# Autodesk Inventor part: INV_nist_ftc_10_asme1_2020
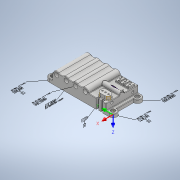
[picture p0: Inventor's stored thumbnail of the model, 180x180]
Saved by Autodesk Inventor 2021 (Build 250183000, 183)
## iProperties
Created: 2016-11
Part Number: INV_nist_ftc_10_asme1_2020
Material: Generic
Document SubType Name: Modeling
Designer: t_liuje
Density: 1 g/cm^3
Appearance: Default
Mass: 187.859 g
Surface Area: 487.851 cm^2
Volume: 187.859 cm^3
Author: t_liuje
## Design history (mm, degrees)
node "Tolerance Features"
  node "Planar Surface 1" dims "d273" = 2.04414 (derived), "d274" = 2.48733 (derived), "d299" = 2.51702 (derived), "d300" = 3.54362 (derived), "d412" = 1.5 (derived), "d413" = 0 (derived), "d414" = 0 (derived), "d978" = 2.99431 (derived), "d979" = 1.44895 (derived), "d980" = 0.2 (derived), "d981" = 0 (derived), "d982" = 0 (derived), "d997" = 3.94736 (derived), "d998" = 10 (derived), "d999" = 0 (derived), "d1001" = 0.25 (derived), "d1002" = 0 (derived), "d1003" = 0 (derived), "d1004" = -22.09829 (derived), "d1005" = 10 (derived), "d1006" = 0 (derived), "d1008" = 0.5 (derived), "d1009" = 0 (derived), "d1010" = 0 (derived)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
  node "Datum Reference Frame 1"
  node "Simple Hole 1" dims "d273" = 2.04414 (derived), "d274" = 2.48733 (derived), "d299" = 2.51702 (derived), "d300" = 3.54362 (derived), "d412" = 1.5 (derived), "d413" = 0 (derived), "d414" = 0 (derived), "d978" = 2.99431 (derived), "d979" = 1.44895 (derived), "d980" = 0.2 (derived), "d981" = 0 (derived), "d982" = 0 (derived), "d997" = 3.94736 (derived), "d998" = 10 (derived), "d999" = 0 (derived), "d1001" = 0.25 (derived), "d1002" = 0 (derived), "d1003" = 0 (derived), "d1004" = -22.09829 (derived), "d1005" = 10 (derived), "d1006" = 0 (derived), "d1008" = 0.5 (derived), "d1009" = 0 (derived), "d1010" = 0 (derived)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
  node "Datum Reference Frame 2"
  node "Simple Hole 2" dims "d273" = 2.04414 (derived), "d274" = 2.48733 (derived), "d299" = 2.51702 (derived), "d300" = 3.54362 (derived), "d412" = 1.5 (derived), "d413" = 0 (derived), "d414" = 0 (derived), "d978" = 2.99431 (derived), "d979" = 1.44895 (derived), "d980" = 0.2 (derived), "d981" = 0 (derived), "d982" = 0 (derived), "d997" = 3.94736 (derived), "d998" = 10 (derived), "d999" = 0 (derived), "d1001" = 0.25 (derived), "d1002" = 0 (derived), "d1003" = 0 (derived), "d1004" = -22.09829 (derived), "d1005" = 10 (derived), "d1006" = 0 (derived), "d1008" = 0.5 (derived), "d1009" = 0 (derived), "d1010" = 0 (derived)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
  node "Datum Reference Frame 3"
  node "Parallel Axes Pattern 1"
  node "Parallel Axes Pattern 2"
  node "General Group 1"
  node "Coplanar Group 1" dims "d273" = 2.04414 (derived), "d274" = 2.48733 (derived), "d299" = 2.51702 (derived), "d300" = 3.54362 (derived), "d412" = 1.5 (derived), "d413" = 0 (derived), "d414" = 0 (derived), "d978" = 2.99431 (derived), "d979" = 1.44895 (derived), "d980" = 0.2 (derived), "d981" = 0 (derived), "d982" = 0 (derived), "d997" = 3.94736 (derived), "d998" = 10 (derived), "d999" = 0 (derived), "d1001" = 0.25 (derived), "d1002" = 0 (derived), "d1003" = 0 (derived), "d1004" = -22.09829 (derived), "d1005" = 10 (derived), "d1006" = 0 (derived), "d1008" = 0.5 (derived), "d1009" = 0 (derived), "d1010" = 0 (derived)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
  node "Datum Reference Frame 4"
  node "Datum Reference Frame 5"
  node "Simple Hole 13" dims "d273" = 2.04414 (derived), "d274" = 2.48733 (derived), "d299" = 2.51702 (derived), "d300" = 3.54362 (derived), "d412" = 1.5 (derived), "d413" = 0 (derived), "d414" = 0 (derived), "d978" = 2.99431 (derived), "d979" = 1.44895 (derived), "d980" = 0.2 (derived), "d981" = 0 (derived), "d982" = 0 (derived), "d997" = 3.94736 (derived), "d998" = 10 (derived), "d999" = 0 (derived), "d1001" = 0.25 (derived), "d1002" = 0 (derived), "d1003" = 0 (derived), "d1004" = -22.09829 (derived), "d1005" = 10 (derived), "d1006" = 0 (derived), "d1008" = 0.5 (derived), "d1009" = 0 (derived), "d1010" = 0 (derived)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
  node "Datum Reference Frame 6"
  node "Datum Reference Frame 12"
  node "Simple Hole 14" dims "d273" = 2.04414 (derived), "d274" = 2.48733 (derived), "d299" = 2.51702 (derived), "d300" = 3.54362 (derived), "d412" = 1.5 (derived), "d413" = 0 (derived), "d414" = 0 (derived), "d978" = 2.99431 (derived), "d979" = 1.44895 (derived), "d980" = 0.2 (derived), "d981" = 0 (derived), "d982" = 0 (derived), "d997" = 3.94736 (derived), "d998" = 10 (derived), "d999" = 0 (derived), "d1001" = 0.25 (derived), "d1002" = 0 (derived), "d1003" = 0 (derived), "d1004" = -22.09829 (derived), "d1005" = 10 (derived), "d1006" = 0 (derived), "d1008" = 0.5 (derived), "d1009" = 0 (derived), "d1010" = 0 (derived)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
  node "Datum Reference Frame 7"
  node "Datum Reference Frame 18"
  node "Datum Reference Frame 13"
  node "Simple Hole 15" dims "d273" = 2.04414 (derived), "d274" = 2.48733 (derived), "d299" = 2.51702 (derived), "d300" = 3.54362 (derived), "d412" = 1.5 (derived), "d413" = 0 (derived), "d414" = 0 (derived), "d978" = 2.99431 (derived), "d979" = 1.44895 (derived), "d980" = 0.2 (derived), "d981" = 0 (derived), "d982" = 0 (derived), "d997" = 3.94736 (derived), "d998" = 10 (derived), "d999" = 0 (derived), "d1001" = 0.25 (derived), "d1002" = 0 (derived), "d1003" = 0 (derived), "d1004" = -22.09829 (derived), "d1005" = 10 (derived), "d1006" = 0 (derived), "d1008" = 0.5 (derived), "d1009" = 0 (derived), "d1010" = 0 (derived)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
  node "Datum Reference Frame 8"
  node "Datum Reference Frame 19"
  node "Datum Reference Frame 14"
  node "Planar Surface 10" dims "d273" = 2.04414 (derived), "d274" = 2.48733 (derived), "d299" = 2.51702 (derived), "d300" = 3.54362 (derived), "d412" = 1.5 (derived), "d413" = 0 (derived), "d414" = 0 (derived), "d978" = 2.99431 (derived), "d979" = 1.44895 (derived), "d980" = 0.2 (derived), "d981" = 0 (derived), "d982" = 0 (derived), "d997" = 3.94736 (derived), "d998" = 10 (derived), "d999" = 0 (derived), "d1001" = 0.25 (derived), "d1002" = 0 (derived), "d1003" = 0 (derived), "d1004" = -22.09829 (derived), "d1005" = 10 (derived), "d1006" = 0 (derived), "d1008" = 0.5 (derived), "d1009" = 0 (derived), "d1010" = 0 (derived)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
  node "Datum Reference Frame 9"
  node "Planar Surface 11" dims "d273" = 2.04414 (derived), "d274" = 2.48733 (derived), "d299" = 2.51702 (derived), "d300" = 3.54362 (derived), "d412" = 1.5 (derived), "d413" = 0 (derived), "d414" = 0 (derived), "d978" = 2.99431 (derived), "d979" = 1.44895 (derived), "d980" = 0.2 (derived), "d981" = 0 (derived), "d982" = 0 (derived), "d997" = 3.94736 (derived), "d998" = 10 (derived), "d999" = 0 (derived), "d1001" = 0.25 (derived), "d1002" = 0 (derived), "d1003" = 0 (derived), "d1004" = -22.09829 (derived), "d1005" = 10 (derived), "d1006" = 0 (derived), "d1008" = 0.5 (derived), "d1009" = 0 (derived), "d1010" = 0 (derived)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
  node "Datum Reference Frame 10"
  node "Planar Surface 12" dims "d273" = 2.04414 (derived), "d274" = 2.48733 (derived), "d299" = 2.51702 (derived), "d300" = 3.54362 (derived), "d412" = 1.5 (derived), "d413" = 0 (derived), "d414" = 0 (derived), "d978" = 2.99431 (derived), "d979" = 1.44895 (derived), "d980" = 0.2 (derived), "d981" = 0 (derived), "d982" = 0 (derived), "d997" = 3.94736 (derived), "d998" = 10 (derived), "d999" = 0 (derived), "d1001" = 0.25 (derived), "d1002" = 0 (derived), "d1003" = 0 (derived), "d1004" = -22.09829 (derived), "d1005" = 10 (derived), "d1006" = 0 (derived), "d1008" = 0.5 (derived), "d1009" = 0 (derived), "d1010" = 0 (derived)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
  node "Datum Reference Frame 11"
  node "Datum Reference Frame 15"
  node "Parallel Axes Pattern 3"
  node "Coplanar Group 2"
  node "Parallel Axes Pattern 4"
  node "Simple Hole 23"
  node "Parallel Axes Pattern 5"
  node "Slot 1" dims "d273" = 2.04414 (derived), "d274" = 2.48733 (derived), "d299" = 2.51702 (derived), "d300" = 3.54362 (derived), "d412" = 1.5 (derived), "d413" = 0 (derived), "d414" = 0 (derived), "d978" = 2.99431 (derived), "d979" = 1.44895 (derived), "d980" = 0.2 (derived), "d981" = 0 (derived), "d982" = 0 (derived), "d997" = 3.94736 (derived), "d998" = 10 (derived), "d999" = 0 (derived), "d1001" = 0.25 (derived), "d1002" = 0 (derived), "d1003" = 0 (derived), "d1004" = -22.09829 (derived), "d1005" = 10 (derived), "d1006" = 0 (derived), "d1008" = 0.5 (derived), "d1009" = 0 (derived), "d1010" = 0 (derived)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
  node "Datum Reference Frame 16"
  node "Datum Reference Frame 17"
  node "Slab 1"
  node "Parallel Axes Pattern 6"
  node "Cylindrical Surface 10"
  node "Parallel Axes Pattern 7"
  node "Parallel Axes Pattern 8"
  node "Parallel Axes Pattern 9"
  node "Parallel Axes Pattern 10"
  node "Simple Hole 51"
  node "Extruded Group 1"
sketch "Sketch1"
  geometry: L1 (-62.5, 23)-(-62.5, 0); L2 (-62.5, 23)-(-22, 23); L3 (-62.5, 0)-(62.5, 0); L4 (62.5, 23)-(60, 23); L5 (62.5, 0)-(62.5, 23); L6 (80.303, 0)-(-60.812, 0); L7 (0, 48.078)-(0, -29.626); C1 r 3.5 at (-14, 23); C2 r 3.5 at (8, 23); C3 r 3.5 at (30, 23); C4 r 3.5 at (52, 23); A1 r 8 centre (-14, 23) between (-9.707, 29.751) and (-22, 23); A2 r 12.5 centre (-3, 40.299) between (-9.707, 29.751) and (3.707, 29.751); A3 r 8 centre (8, 23) between (12.293, 29.751) and (3.707, 29.751); A4 r 12.5 centre (19, 40.299) between (12.293, 29.751) and (25.707, 29.751); A5 r 8 centre (30, 23) between (34.293, 29.751) and (25.707, 29.751); A6 r 12.5 centre (41, 40.299) between (34.293, 29.751) and (47.707, 29.751); A7 r 8 centre (52, 23) between (60, 23) and (47.707, 29.751); 1 further point
  constraints: 14 end point, 14 point on circle, 11 centre point, 8 equal radius, 7 point on line, 6 tangent, 4 coincident, 2 collinear, 2 horizontal, 2 vertical, 1 other
  dimensions: "d0" = 125 distance of L1.end L3.end; "d1" = 10.5 distance from line of L5 A7.centre; "d2" = 23 distance of L1.start L1.end; "d3" = 8 radius of A7; "d4" = 22 distance of C3.centre C4.centre (= d5); "d5" = 22 distance of A1.centre A3.centre; "d6" = 22 distance of C3.centre A3.centre (= d5); "d7" = 12.5 radius of A6; "d8" = 7 diameter of C4
extrude "Extrusion1" new body sketch "Sketch1" stored distance "d9" = 75; taper "d10" = 0 deg
sketch "Sketch2"
  geometry: L1 (125, 0)-(125, -75) reference; L2 (0, 0)-(125, 0) reference; L3 (0, -75)-(0, 0) reference; L4 (125, -75)-(0, -75) reference; L5 (125, 0)-(132.5, 0); L6 (132.5, -18)-(132.5, -57); L7 (132.5, -75)-(125, -75); L8 (125, -75)-(125, 0); L9 (0, 0)-(-7.5, 0); L10 (-7.5, -18)-(-7.5, -57); L11 (-7.5, -75)-(0, -75); L12 (0, -75)-(0, 0); A1 r 9 centre (132.5, -9) between (132.5, -18) and (132.5, 0); A2 r 9 centre (132.5, -66) between (132.5, -75) and (132.5, -57); A3 r 9 centre (-7.5, -9) between (-7.5, 0) and (-7.5, -18); A4 r 9 centre (-7.5, -66) between (-7.5, -57) and (-7.5, -75); 1 further point
  constraints: 16 end point, 8 point on circle, 4 centre point, 4 parallel, 4 point on line, 4 tangent, 3 equal radius, 2 collinear, 2 horizontal, 2 perpendicular
  dimensions: "d11" = 7.5 distance of L1.start L5.end; "d12" = 18 distance of L6.start L5.end; "d13" = 18 distance of L6.end L7.start
extrude "Extrusion2" join sketch "Sketch2" distance "d14" = 8; taper "d15" = 0 deg
sketch "Sketch3"
  geometry: L1 (21, -53.5)-(30, -53.5); L2 (30, -68.5)-(21, -68.5); L3 (40.5, -75)-(0, -75) reference; L4 (40.5, 0)-(40.5, -75) reference; A1 r 7.5 centre (30, -61) between (30, -68.5) and (30, -53.5); A2 r 7.5 centre (21, -61) between (21, -53.5) and (21, -68.5); 1 further point
  constraints: 4 end point, 4 point on circle, 4 tangent, 2 centre point, 1 horizontal, 1 parallel
  dimensions: "d16" = 9 distance of L2.start L2.end; "d17" = 15 distance of L1.end L2.start; "d18" = 6.5 distance between parallel lines of L3 L2; "d19" = 10.5 distance from line of L4 A1.centre
extrude "Extrusion3" join sketch "Sketch3" distance "d20" = 8; taper "d21" = 0 deg
sketch "Sketch4"
  geometry: L1 (33, -75)-(33, -70); L2 (33, -70)-(28, -70); L3 (28, -70)-(28, -74); L4 (28, -74)-(23, -74); L5 (23, -74)-(23, -70); L6 (23, -70)-(18, -70); L7 (18, -70)-(18, -75); L8 (18, -75)-(33, -75); L9 (40.5, -75)-(0, -75) reference; L10 (40.5, 0)-(40.5, -75) reference; 1 further point
  constraints: 16 end point, 5 perpendicular, 2 collinear, 2 point on line, 1 vertical
  dimensions: "d22" = 5 distance of L1.start L1.end; "d23" = 5 distance of L1.end L2.end; "d24" = 4 distance of L2.end L3.end; "d25" = 5 distance of L3.end L4.end; "d26" = 5 distance of L5.end L6.end; "d27" = 7.5 distance between parallel lines of L10 L1
extrude "Extrusion4" cut sketch "Sketch4" stored distance "d28" = 8; taper "d29" = 0 deg
sketch "Sketch5"
  geometry: L1 (7.5, -5)-(37.5, -5); L2 (37.5, -5)-(37.5, -20); L3 (37.5, -20)-(7.5, -20); L4 (7.5, -20)-(7.5, -5); L5 (0, 0)-(40.5, 0) reference; L6 (40.5, 0)-(40.5, -75) reference; 1 further point
  constraints: 8 end point, 2 parallel, 1 horizontal, 1 perpendicular
  dimensions: "d30" = 30 distance of L2.end L3.end; "d31" = 15 distance of L1.end L2.end; "d32" = 5 distance between parallel lines of L1 L5; "d33" = 3 distance between parallel lines of L2 L6
extrude "Extrusion5" join sketch "Sketch5" distance "d34" = 4; taper "d35" = 0 deg
sketch "Sketch6"
  geometry: L1 (7.5, -5)-(37.5, -5) reference; L2 (7.5, -20)-(7.5, -5) reference; L3 (37.5, -5)-(37.5, -20) reference; L4 (37.5, -20)-(7.5, -20) reference; L5 (15.5, -5)-(18.5, -5); L6 (18.5, -5)-(18.5, -20); L7 (18.5, -20)-(15.5, -20); L8 (15.5, -20)-(15.5, -5); L9 (26.5, -5)-(29.5, -5); L10 (29.5, -5)-(29.5, -20); L11 (29.5, -20)-(26.5, -20); L12 (26.5, -20)-(26.5, -5); 1 further point
  constraints: 16 end point, 4 parallel, 4 point on line, 2 horizontal, 2 perpendicular
  dimensions: "d36" = 3 distance between parallel lines of L10 L12; "d37" = 8 distance between parallel lines of L3 L10; "d38" = 8 distance between parallel lines of L12 L6; "d39" = 3 distance between parallel lines of L8 L6
extrude "Extrusion6" cut sketch "Sketch6" distance "d40" = 1.5; taper "d41" = 0 deg
sketch "Sketch7"
  geometry: L1 (0, 75)-(0, 0) reference; A1 r 6 centre (0, 37.5) between (0, 43.5) and (0, 31.5); 1 further point
  constraints: 2 point on circle, 2 point on line, 1 centre point, 1 midpoint
  dimensions: "d42" = 12 diameter of A1
extrude "Extrusion7" join sketch "Sketch7" stored distance "d43" = 1.5; taper "d44" = 0 deg; dims "d4" = 22 (= d5)
fillet "Fillet1" dims "d45" = 1
sketch "Sketch11"
  geometry: A1 r 9 centre (-132.5, -9) between (-132.5, 0) and (-132.5, -18) reference; 3 further points
  constraints: 2 coincident
hole "Hole2" sketch "Sketch11" diameter "d57" = 6; stored, may be unused: countersink angle "d61" = 90 deg, drill point angle "d63" = 0 deg; dims "d58" = 6, "d59" = 10, "d60" = 2, "d62" = 8
sketch "Sketch12"
  geometry: C1 r 3.5 at (-52, -23) reference; C2 r 3.5 at (-30, -23) reference; C3 r 3.5 at (-8, -23) reference; C4 r 3.5 at (14, -23) reference; 4 further points
  constraints: 4 coincident
hole "Hole6" sketch "Sketch12" at (-52, -23), (-30, -23), (-8, -23), (14, -23) diameter "d93" = 10; stored, may be unused: countersink angle "d97" = 90 deg, drill point angle "d99" = 0 deg; dims "d94" = 6, "d95" = 10, "d96" = 2, "d98" = 10
hole "Hole7" diameter "d102" = 3.5; stored, may be unused: countersink angle "d106" = 90 deg, drill point angle "d108" = 0 deg; dims "d100" = 14, "d101" = 8, "d103" = 6, "d104" = 10, "d105" = 2, "d107" = 10.25
pattern_linear "Rectangular Pattern1" dims "d111" = 7
sketch "Sketch18" dims "d944" = 10
  geometry: L1 (29.5, -20)-(36.5, -20) reference; L2 (37.5, -19)-(37.5, -6) reference; C1 r 1.75 at (11.5, -12.5); C2 r 1.75 at (33.5, -12.5); 3 further points
  constraints: 2 centre point, 2 coincident, 1 horizontal, 2 other
  dimensions: "d112" = 7.5 distance from line of L1 point (33.5, -12.5); "d113" = 4 distance from line of L2 point (33.5, -12.5); "d941" = 11 distance of point (33.5, -12.5) point (22.5, -12.5); "d1056" = 3.5 diameter of C1; "d1069" = 3.5 diameter of C2
sketch "Sketch15"
  geometry: L1 (37.5, -19)-(37.5, -6) reference; L2 (29.5, -20)-(36.5, -20) reference; L3 (29.5, -5)-(29.5, -20) reference; L4 (29.5, -5)-(29.5, -20) reference; L5 (29.5, -16.191)-(37.5, -16.191); L6 (33.5, -16.191)-(33.5, -8.753); L7 (29.5, -12.5)-(36.185, -12.5); L8 (29.5, -20)-(29.5, -5); 2 further points
  constraints: 8 end point, 2 midpoint, 2 point on line, 2 symmetric about line, 1 horizontal, 1 perpendicular, 1 vertical
  dimensions: "d121" = 2.4 distance from line of L1 point (35.1, -17.5); "d122" = 2.5 distance from line of L2 point (35.1, -17.5)
hole "Hole9" sketch "Sketch15" at (35.1, -17.5), (31.9, -7.5) diameter "d123" = 2.459; stored, may be unused: countersink angle "d127" = 90 deg, drill point angle "d129" = 118 deg; dims "d124" = 6, "d125" = 10, "d126" = 2, "d128" = 12
sketch "Sketch8"
  geometry: L1 (-12, -5.5)-(-90, -5.5); L2 (-90, -5.5)-(-90, 44.5); L3 (-90, 44.5)-(-12, 44.5); L4 (-12, 44.5)-(-12, -5.5); L5 (0, 0)-(0, 39) reference; L6 (-110, -18)-(0, -18) reference; 1 further point
  constraints: 8 end point, 2 parallel, 1 horizontal, 1 perpendicular
  dimensions: "d142" = 78 distance of L2.end L3.end; "d143" = 50 distance of L1.end L2.end; "d144" = 12 distance between parallel lines of L5 L4; "d145" = 12.5 distance between parallel lines of L1 L6
extrude "Extrusion8" cut sketch "Sketch8" distance "d146" = 17; taper "d147" = 0 deg
fillet "Fillet2" dims "d148" = 2
hole "Hole11" diameter "d151" = 2.5; stored, may be unused: countersink angle "d155" = 90 deg, drill point angle "d157" = 118 deg; dims "d149" = 22, "d150" = 18, "d152" = 6, "d153" = 10, "d154" = 2, "d156" = 12
pattern_linear "Rectangular Pattern3" dims "d160" = 22, "d163" = 31
hole "Hole12" diameter "d287" = 5.5; stored, may be unused: countersink angle "d291" = 90 deg, drill point angle "d293" = 118 deg; dims "d285" = 14, "d286" = 5, "d288" = 6, "d289" = 4, "d290" = 2, "d292" = 27.5
hole "Hole13" diameter "d330" = 5.5; stored, may be unused: countersink angle "d334" = 90 deg, drill point angle "d336" = 118 deg; dims "d328" = 8.062, "d329" = 12.54, "d331" = 6, "d332" = 4, "d333" = 2, "d335" = 35
workplane "Work Plane2"
sketch "Sketch9"
  geometry: L1 (-26.77, 0)-(-11.77, 0)
  constraints: 2 end point, 1 horizontal
  dimensions: "d370" = 15 distance of L1.start L1.end
workplane "Work Plane3"
workplane "Work Plane4"
workplane "Work Plane5"
workplane "Work Plane6"
workplane "Work Plane7"
workplane "Work Plane8"
sketch "Sketch10"
  geometry: 1 further point
fillet "Fillet3" dims "d870" = 0.15
sketch "Sketch13"
  geometry: C1 r 3.5 at (14, 23) reference; C2 r 3.5 at (-8, 23) reference; C3 r 3.5 at (-30, 23) reference; C4 r 3.5 at (-52, 23) reference; 5 further points
  constraints: 4 coincident
hole "Hole14" sketch "Sketch13" at (14, 23), (-8, 23), (-30, 23), (-52, 23) diameter "d901" = 10; stored, may be unused: countersink angle "d905" = 90 deg, drill point angle "d907" = 0 deg; dims "d902" = 6, "d903" = 4, "d904" = 2, "d906" = 10
mirror "Mirror3"
sketch "Sketch14"
  geometry: C1 r 3 at (7.5, -9) reference; C2 r 3 at (-132.5, -9) reference; C3 r 3 at (-132.5, -9) reference; C4 r 3 at (7.5, -9) reference; C5 r 3 at (-132.5, -66) reference; C6 r 3 at (7.5, -66) reference; 5 further points
  constraints: 4 coincident
hole "Hole15" sketch "Sketch14" at (7.5, -9), (7.5, -66), (-132.5, -66), (-132.5, -9) diameter "d908" = 10; stored, may be unused: countersink angle "d912" = 90 deg, drill point angle "d914" = 0 deg; dims "d909" = 6, "d910" = 4, "d911" = 2, "d913" = 2
fillet "Fillet4" dims "d875" = 0.2
sketch "Sketch16"
  geometry: L1 (26.5, -19)-(26.5, -6); L2 (7.5, -20)-(25.5, -20); L3 (29.5, -20)-(26.5, -20) reference; L4 (18.5, -20)-(26.5, -20) reference; L5 (26.5, -5)-(18.5, -5) reference; L6 (18.5, -5)-(18.5, -20) reference; 3 further points
  constraints: 4 end point
  dimensions: "d915" = 2.4 distance from line of L1 point (24.1, -17.5); "d916" = 2.5 distance from line of L2 point (24.1, -17.5); "d917" = 2.5 distance from line of L5 point (20.9, -7.5); "d918" = 2.4 distance from line of L6 point (20.9, -7.5)
hole "Hole16" sketch "Sketch16" at (24.1, -17.5), (20.9, -7.5) diameter "d919" = 2.459; stored, may be unused: countersink angle "d923" = 90 deg, drill point angle "d925" = 118 deg; dims "d920" = 6, "d921" = 4, "d922" = 2, "d924" = 12
sketch "Sketch17"
  geometry: L1 (37.5, -19)-(37.5, -6); L2 (29.5, -20)-(36.5, -20); L3 (29.5, -5)-(29.5, -20); L4 (29.5, -5)-(29.5, -20); L5 (29.5, -16.191)-(37.5, -16.191); L6 (33.5, -16.191)-(33.5, -8.753); L7 (29.5, -12.5)-(36.185, -12.5); L8 (29.5, -20)-(29.5, -5); L9 (15.5, -19)-(15.5, -6); L10 (7.5, -20)-(14.5, -20); L11 (29.5, -20)-(26.5, -20); L12 (7.5, -20)-(15.5, -20); L13 (15.5, -5)-(7.5, -5); L14 (7.5, -5)-(7.5, -20); L15 (15.5, -20)-(15.5, -5) reference; C1 r 1.75 at (22.5, -12.5); 7 further points
  constraints: 28 end point, 2 midpoint, 2 point on line, 2 symmetric about line, 1 centre point, 1 coincident, 1 horizontal, 1 perpendicular, 1 vertical
  dimensions: "d926" = 2.4 distance from line of L1 point (35.1, -17.5); "d927" = 2.5 distance from line of L2 point (35.1, -17.5); "d928" = 2.4 distance from line of L9 point (13.1, -17.5); "d929" = 2.5 distance from line of L10 point (13.1, -17.5); "d930" = 2.5 distance from line of L13 point (9.9, -7.5); "d931" = 2.4 distance from line of L14 point (9.9, -7.5); "d1066" = 3.5 diameter of C1 (derived)
hole "Hole17" sketch "Sketch17" diameter "d932" = 2.459; stored, may be unused: countersink angle "d936" = 90 deg, drill point angle "d938" = 118 deg; dims "d933" = 6, "d934" = 4, "d935" = 2, "d937" = 12
extrude "Extrusion10" cut sketch "Sketch18" distance "d1057" = 9.25; taper "d1058" = 0 deg
extrude "Extrusion11" cut sketch "Sketch17" distance "d1067" = 9.25; taper "d1068" = 0 deg
extrude "Extrusion12" cut sketch "Sketch18" distance "d1070" = 9.25; taper "d1071" = 0 deg
sketch "Sketch20"
  geometry: L1 (-1.061, 8)-(5.303, 8) reference; L2 (3.544, 8)-(-4.428, 8); L3 (-4.428, 8)-(-4.428, -0.058); L4 (-4.428, -0.058)-(3.544, -0.058); L5 (3.544, -0.058)-(3.544, 8); 1 further point
  constraints: 8 end point, 2 parallel, 1 horizontal, 1 perpendicular, 1 point on line
patch "Boundary Patch1" sketch "Sketch20"
sketch "Sketch21"
  geometry: L1 (7.5, 8)-(-5.303, 8) reference; L2 (-8.827, 0)-(18.436, 0) reference; L3 (-1.99, 8)-(4.804, 8); L4 (4.804, 8)-(4.804, 0); L5 (4.804, 0)-(-1.99, 0); L6 (-1.99, 0)-(-1.99, 8); 2 further points
  constraints: 8 end point, 2 parallel, 1 horizontal, 1 midpoint, 1 perpendicular, 1 point on line
patch "Boundary Patch2" sketch "Sketch21"
body "Solid1"
node "Annotations"
node "Projected Loop1"
body "Srf1"
body "Srf2"
node "Leader Text 3"
node "Leader Text 6"
node "General Note 1"
node "General Surface Profile Tolerance"
node "Feature Control Frame 30"
node "Datum Identifier 1" dims "d5" = 22, "d273" = 2.04414 (derived), "d274" = 2.48733 (derived), "d299" = 2.51702 (derived), "d300" = 3.54362 (derived), "d412" = 1.5 (derived), "d413" = 0 (derived), "d414" = 0 (derived), "d978" = 2.99431 (derived), "d979" = 1.44895 (derived), "d980" = 0.2 (derived), "d981" = 0 (derived), "d982" = 0 (derived), "d997" = 3.94736 (derived), "d998" = 10 (derived), "d999" = 0 (derived), "d1001" = 0.25 (derived), "d1002" = 0 (derived), "d1003" = 0 (derived), "d1004" = -22.09829 (derived), "d1005" = 10 (derived), "d1006" = 0 (derived), "d1008" = 0.5 (derived), "d1009" = 0 (derived)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
node "Hole Note 1" dims "d5" = 22
node "Feature Control Frame 31"
node "Datum Identifier 2" dims "d5" = 22, "d273" = 2.04414 (derived), "d274" = 2.48733 (derived), "d299" = 2.51702 (derived), "d300" = 3.54362 (derived), "d412" = 1.5 (derived), "d413" = 0 (derived), "d414" = 0 (derived), "d978" = 2.99431 (derived), "d979" = 1.44895 (derived), "d980" = 0.2 (derived), "d981" = 0 (derived), "d982" = 0 (derived), "d997" = 3.94736 (derived), "d998" = 10 (derived), "d999" = 0 (derived), "d1001" = 0.25 (derived), "d1002" = 0 (derived), "d1003" = 0 (derived), "d1004" = -22.09829 (derived), "d1005" = 10 (derived), "d1006" = 0 (derived), "d1008" = 0.5 (derived), "d1009" = 0 (derived)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
node "Hole Note 2" dims "d5" = 22
node "Feature Control Frame 32"
node "Datum Identifier 3" dims "d5" = 22, "d273" = 2.04414 (derived), "d274" = 2.48733 (derived), "d299" = 2.51702 (derived), "d300" = 3.54362 (derived), "d412" = 1.5 (derived), "d413" = 0 (derived), "d414" = 0 (derived), "d978" = 2.99431 (derived), "d979" = 1.44895 (derived), "d980" = 0.2 (derived), "d981" = 0 (derived), "d982" = 0 (derived), "d997" = 3.94736 (derived), "d998" = 10 (derived), "d999" = 0 (derived), "d1001" = 0.25 (derived), "d1002" = 0 (derived), "d1003" = 0 (derived), "d1004" = -22.09829 (derived), "d1005" = 10 (derived), "d1006" = 0 (derived), "d1008" = 0.5 (derived), "d1009" = 0 (derived)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
node "Simple Hole 3"
node "Simple Hole 4"
node "Hole Note 3" dims "d5" = 22
node "Feature Control Frame 33"
node "Simple Hole 5"
node "Simple Hole 6"
node "Simple Hole 7"
node "Simple Hole 8"
node "Simple Hole 9"
node "Simple Hole 10"
node "Simple Hole 11"
node "Simple Hole 12"
node "Hole Note 4" dims "d5" = 22
node "Feature Control Frame 34"
node "Planar Surface 2"
node "Planar Surface 3"
node "Cylindrical Surface 1"
node "Cylindrical Surface 2"
node "Cylindrical Surface 3"
node "Spherical Surface 1"
node "Planar Surface 4"
node "Cylindrical Surface 4"
node "Planar Surface 5"
node "Cylindrical Surface 5"
node "Spherical Surface 2"
node "Cylindrical Surface 6"
node "Cylindrical Surface 7"
node "Planar Surface 6"
node "Spherical Surface 3"
node "Spherical Surface 4"
node "Cylindrical Surface 8"
node "Feature Control Frame 35"
node "Leader Text 7"
node "Planar Surface 7"
node "Planar Surface 8"
node "Planar Surface 9"
node "Feature Control Frame 36"
node "Datum Identifier 4" dims "d5" = 22, "d273" = 2.04414 (derived), "d274" = 2.48733 (derived), "d299" = 2.51702 (derived), "d300" = 3.54362 (derived), "d412" = 1.5 (derived), "d413" = 0 (derived), "d414" = 0 (derived), "d978" = 2.99431 (derived), "d979" = 1.44895 (derived), "d980" = 0.2 (derived), "d981" = 0 (derived), "d982" = 0 (derived), "d997" = 3.94736 (derived), "d998" = 10 (derived), "d999" = 0 (derived), "d1001" = 0.25 (derived), "d1002" = 0 (derived), "d1003" = 0 (derived), "d1004" = -22.09829 (derived), "d1005" = 10 (derived), "d1006" = 0 (derived), "d1008" = 0.5 (derived), "d1009" = 0 (derived)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
node "Leader Text 8"
node "Diameter Dimension 1" dims "d5" = 22, "d1089" = 3.5 (derived)
node "Feature Control Frame 40"
node "Datum Identifier 5" dims "d5" = 22, "d273" = 2.04414 (derived), "d274" = 2.48733 (derived), "d299" = 2.51702 (derived), "d300" = 3.54362 (derived), "d412" = 1.5 (derived), "d413" = 0 (derived), "d414" = 0 (derived), "d978" = 2.99431 (derived), "d979" = 1.44895 (derived), "d980" = 0.2 (derived), "d981" = 0 (derived), "d982" = 0 (derived), "d997" = 3.94736 (derived), "d998" = 10 (derived), "d999" = 0 (derived), "d1001" = 0.25 (derived), "d1002" = 0 (derived), "d1003" = 0 (derived), "d1004" = -22.09829 (derived), "d1005" = 10 (derived), "d1006" = 0 (derived), "d1008" = 0.5 (derived), "d1009" = 0 (derived)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
node "Diameter Dimension 2" dims "d5" = 22, "d1099" = 3.5 (derived)
node "Feature Control Frame 41"
node "Datum Identifier 6" dims "d5" = 22, "d273" = 2.04414 (derived), "d274" = 2.48733 (derived), "d299" = 2.51702 (derived), "d300" = 3.54362 (derived), "d412" = 1.5 (derived), "d413" = 0 (derived), "d414" = 0 (derived), "d978" = 2.99431 (derived), "d979" = 1.44895 (derived), "d980" = 0.2 (derived), "d981" = 0 (derived), "d982" = 0 (derived), "d997" = 3.94736 (derived), "d998" = 10 (derived), "d999" = 0 (derived), "d1001" = 0.25 (derived), "d1002" = 0 (derived), "d1003" = 0 (derived), "d1004" = -22.09829 (derived), "d1005" = 10 (derived), "d1006" = 0 (derived), "d1008" = 0.5 (derived), "d1009" = 0 (derived)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
node "Diameter Dimension 3" dims "d5" = 22, "d1109" = 3.5 (derived)
node "Feature Control Frame 42"
node "Datum Identifier 7" dims "d5" = 22, "d273" = 2.04414 (derived), "d274" = 2.48733 (derived), "d299" = 2.51702 (derived), "d300" = 3.54362 (derived), "d412" = 1.5 (derived), "d413" = 0 (derived), "d414" = 0 (derived), "d978" = 2.99431 (derived), "d979" = 1.44895 (derived), "d980" = 0.2 (derived), "d981" = 0 (derived), "d982" = 0 (derived), "d997" = 3.94736 (derived), "d998" = 10 (derived), "d999" = 0 (derived), "d1001" = 0.25 (derived), "d1002" = 0 (derived), "d1003" = 0 (derived), "d1004" = -22.09829 (derived), "d1005" = 10 (derived), "d1006" = 0 (derived), "d1008" = 0.5 (derived), "d1009" = 0 (derived)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
node "Feature Control Frame 43"
node "Datum Identifier 8" dims "d5" = 22, "d273" = 2.04414 (derived), "d274" = 2.48733 (derived), "d299" = 2.51702 (derived), "d300" = 3.54362 (derived), "d412" = 1.5 (derived), "d413" = 0 (derived), "d414" = 0 (derived), "d978" = 2.99431 (derived), "d979" = 1.44895 (derived), "d980" = 0.2 (derived), "d981" = 0 (derived), "d982" = 0 (derived), "d997" = 3.94736 (derived), "d998" = 10 (derived), "d999" = 0 (derived), "d1001" = 0.25 (derived), "d1002" = 0 (derived), "d1003" = 0 (derived), "d1004" = -22.09829 (derived), "d1005" = 10 (derived), "d1006" = 0 (derived), "d1008" = 0.5 (derived), "d1009" = 0 (derived)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
node "Datum Identifier 9" dims "d5" = 22, "d273" = 2.04414 (derived), "d274" = 2.48733 (derived), "d299" = 2.51702 (derived), "d300" = 3.54362 (derived), "d412" = 1.5 (derived), "d413" = 0 (derived), "d414" = 0 (derived), "d978" = 2.99431 (derived), "d979" = 1.44895 (derived), "d980" = 0.2 (derived), "d981" = 0 (derived), "d982" = 0 (derived), "d997" = 3.94736 (derived), "d998" = 10 (derived), "d999" = 0 (derived), "d1001" = 0.25 (derived), "d1002" = 0 (derived), "d1003" = 0 (derived), "d1004" = -22.09829 (derived), "d1005" = 10 (derived), "d1006" = 0 (derived), "d1008" = 0.5 (derived), "d1009" = 0 (derived)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
node "Datum Identifier 10" dims "d5" = 22, "d273" = 2.04414 (derived), "d274" = 2.48733 (derived), "d299" = 2.51702 (derived), "d300" = 3.54362 (derived), "d412" = 1.5 (derived), "d413" = 0 (derived), "d414" = 0 (derived), "d978" = 2.99431 (derived), "d979" = 1.44895 (derived), "d980" = 0.2 (derived), "d981" = 0 (derived), "d982" = 0 (derived), "d997" = 3.94736 (derived), "d998" = 10 (derived), "d999" = 0 (derived), "d1001" = 0.25 (derived), "d1002" = 0 (derived), "d1003" = 0 (derived), "d1004" = -22.09829 (derived), "d1005" = 10 (derived), "d1006" = 0 (derived), "d1008" = 0.5 (derived), "d1009" = 0 (derived)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
node "Planar Surface 13"
node "Planar Surface 14"
node "Feature Control Frame 45"
node "Leader Text 10"
node "Simple Hole 20"
node "Simple Hole 21"
node "Simple Hole 22"
node "Hole Note 6" dims "d5" = 22
node "Feature Control Frame 46"
node "Hole Note 7" dims "d5" = 22
node "Feature Control Frame 47"
node "Leader Text 11"
node "Planar Surface 16"
node "Planar Surface 17"
node "Linear Dimension 1" dims "d5" = 22, "d1217" = 15 (derived)
node "Feature Control Frame 51"
node "Datum Identifier 11" dims "d5" = 22, "d273" = 2.04414 (derived), "d274" = 2.48733 (derived), "d299" = 2.51702 (derived), "d300" = 3.54362 (derived), "d412" = 1.5 (derived), "d413" = 0 (derived), "d414" = 0 (derived), "d978" = 2.99431 (derived), "d979" = 1.44895 (derived), "d980" = 0.2 (derived), "d981" = 0 (derived), "d982" = 0 (derived), "d997" = 3.94736 (derived), "d998" = 10 (derived), "d999" = 0 (derived), "d1001" = 0.25 (derived), "d1002" = 0 (derived), "d1003" = 0 (derived), "d1004" = -22.09829 (derived), "d1005" = 10 (derived), "d1006" = 0 (derived), "d1008" = 0.5 (derived), "d1009" = 0 (derived)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
node "Planar Surface 18"
node "Planar Surface 19"
node "Linear Dimension 2" dims "d5" = 22, "d1250" = 5 (derived)
node "Feature Control Frame 52"
node "Simple Hole 28"
node "Simple Hole 29"
node "Simple Hole 30"
node "Simple Hole 31"
node "Hole Note 9" dims "d5" = 22
node "Feature Control Frame 53"
node "Feature Control Frame 54"
node "Simple Hole 41"
node "Simple Hole 42"
node "Hole Note 13" dims "d5" = 22
node "Feature Control Frame 58"
node "Simple Hole 43"
node "Simple Hole 44"
node "Hole Note 14" dims "d5" = 22
node "Feature Control Frame 59"
node "Simple Hole 45"
node "Simple Hole 46"
node "Hole Note 15" dims "d5" = 22
node "Feature Control Frame 60"
node "Simple Hole 47"
node "Simple Hole 48"
node "Simple Hole 49"
node "Simple Hole 50"
node "Diameter Dimension 7" dims "d5" = 22, "d1339" = 7 (derived)
node "Feature Control Frame 61"
node "Radial Dimension 1" dims "d5" = 22, "d1345" = 0.2 (derived)
node "Radial Dimension 2" dims "d5" = 22, "d1349" = 0.15 (derived)
node "Hole Note 16" dims "d5" = 22
node "Feature Control Frame 62"
node "Leader Text 17"
node "Simple Hole 52"
node "Simple Hole 53"
node "Simple Hole 54"
node "Simple Hole 55"
node "Hole Note 17" dims "d5" = 22
node "Feature Control Frame 63"
node "Leader Text 18"
node "Leader Text 19"
node "Simple Hole 56"
node "Simple Hole 57"
node "Simple Hole 58"
node "Simple Hole 59"
node "Hole Note 18" dims "d5" = 22
node "Feature Control Frame 64"
node "Leader Text 20"
node "Leader Text 21"
node "Planar Surface 20"
node "Cylindrical Surface 11"
node "Planar Surface 21"
node "Cylindrical Surface 12"
node "Feature Control Frame 65"
other parameters: "d410" = 45 deg, "d411" = -45 deg, "d415" = 0, "d416" = 0, "d417" = 0, "d418" = -90 deg, "d419" = 0, "d420" = 0, "d421" = 8, "d422" = 0, "d423" = 0, "d424" = 0, "d425" = 0, "d426" = -90 deg, "d960" = 0, "d961" = 0, "d962" = 0, "d963" = 0, "d964" = 0, "d965" = 0, "d966" = 0, "d967" = 0, "d968" = 0, "d969" = 0, "d970" = 0, "d971" = 0, "d972" = 0, "d973" = 0, "d974" = 0, "d975" = 0, "d976" = 0, "d977" = 0
